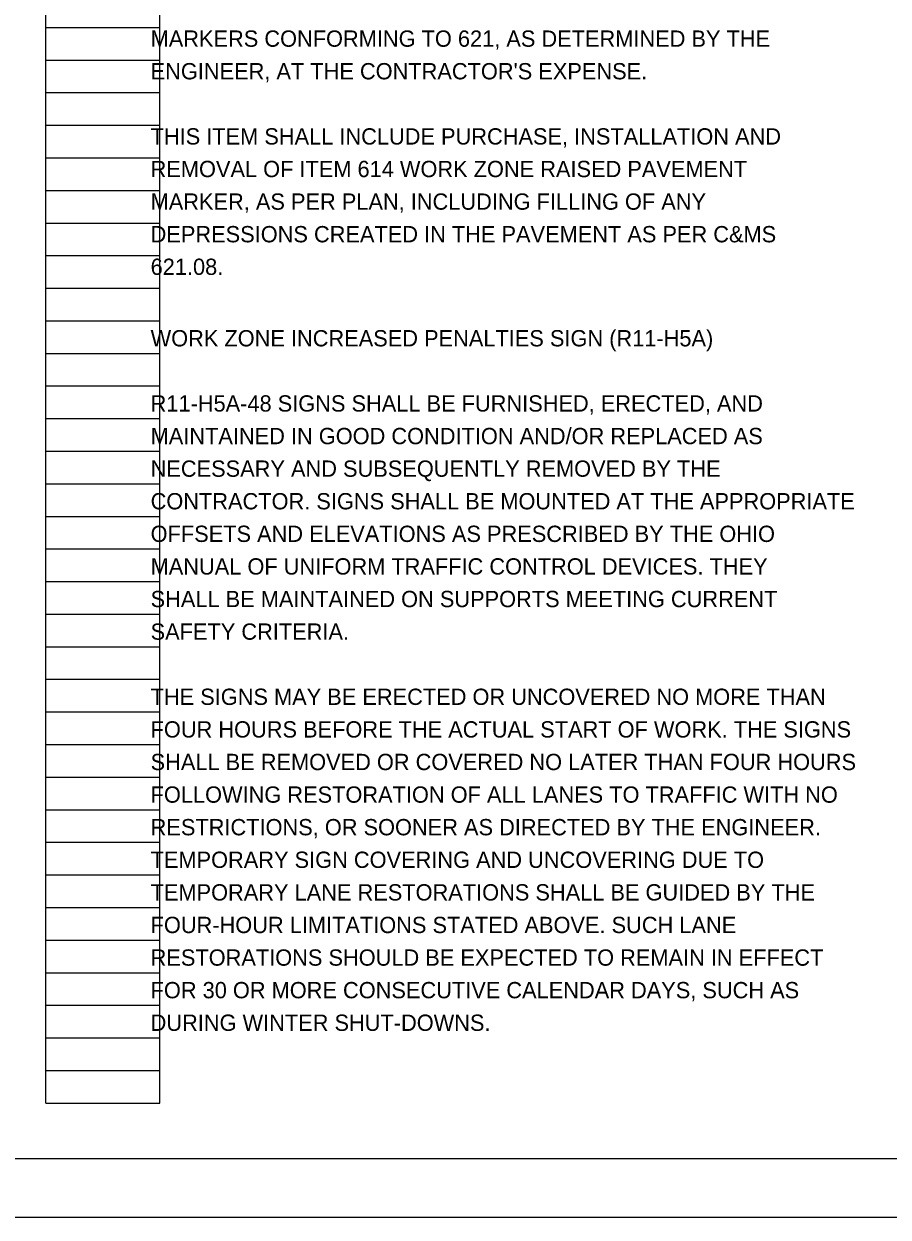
# Model space of a CAD drawing. Extents: x 0 to 34, y 0 to 22.
# Drawn here: x 16.07 to 23.5, y 0 to 10.25 of the extents above; entities that cross this region are included whole.
import ezdxf

# ---------------------------------------------------------------- set-up
doc = ezdxf.new("R2010")
doc.units = 0
for name, color, linetype in [('SH_Border', 7, 'Continuous'), ('SH_Cut_Line', 7, 'Continuous'), ('SH_Data', 7, 'Continuous'), ('SH_Text', 7, 'Continuous')]:
    doc.layers.add(name, color=color, linetype=linetype)

msp = doc.modelspace()

# ---------------------------------------------------------------- linework, layer by layer
at = {"layer": 'SH_Border'}
msp.add_lwpolyline([(1.5, 21.5), (33.5, 21.5), (33.5, 0.5), (1.5, 0.5)], close=True, dxfattribs=at)
at = {"layer": 'SH_Cut_Line'}
msp.add_lwpolyline([(0, 0), (34, 0), (34, 22), (0, 22)], close=True, dxfattribs=at)
at = {"layer": 'SH_Data'}
for p, q in [((16.26, 0.98), (16.26, 21.14)), ((17.24, 0.98), (17.24, 21.14)), ((16.26, 10.22), (17.24, 10.22)), ((16.26, 9.94), (17.24, 9.94)), ((16.26, 9.66), (17.24, 9.66)), ((16.26, 9.38), (17.24, 9.38)), ((16.26, 9.1), (17.24, 9.1)), ((16.26, 8.82), (17.24, 8.82)), ((16.26, 8.54), (17.24, 8.54)), ((16.26, 8.26), (17.24, 8.26)), ((16.26, 7.98), (17.24, 7.98)), ((16.26, 7.7), (17.24, 7.7)), ((16.26, 7.42), (17.24, 7.42)), ((16.26, 7.14), (17.24, 7.14)), ((16.26, 6.86), (17.24, 6.86)), ((16.26, 6.58), (17.24, 6.58)), ((16.26, 6.3), (17.24, 6.3)), ((16.26, 6.02), (17.24, 6.02)), ((16.26, 5.74), (17.24, 5.74)), ((16.26, 5.46), (17.24, 5.46)), ((16.26, 5.18), (17.24, 5.18)), ((16.26, 4.9), (17.24, 4.9)), ((16.26, 4.62), (17.24, 4.62)), ((16.26, 4.34), (17.24, 4.34)), ((16.26, 4.06), (17.24, 4.06)), ((16.26, 3.78), (17.24, 3.78)), ((16.26, 3.5), (17.24, 3.5)), ((16.26, 3.22), (17.24, 3.22)), ((16.26, 2.94), (17.24, 2.94)), ((16.26, 2.66), (17.24, 2.66)), ((16.26, 2.38), (17.24, 2.38)), ((16.26, 2.1), (17.24, 2.1)), ((16.26, 1.82), (17.24, 1.82)), ((16.26, 1.54), (17.24, 1.54)), ((16.26, 1.26), (17.24, 1.26)), ((16.26, 0.98), (17.24, 0.98))]:
    msp.add_line(p, q, dxfattribs=at)

# ---------------------------------------------------------------- texts
at = {"layer": 'SH_Text'}
for s, p in [('MARKERS CONFORMING TO 621, AS DETERMINED BY THE', (17.16, 10.054)), ("ENGINEER, AT THE CONTRACTOR'S EXPENSE.", (17.16, 9.774)), ('THIS ITEM SHALL INCLUDE PURCHASE, INSTALLATION AND', (17.16, 9.214)), ('REMOVAL OF ITEM 614 WORK ZONE RAISED PAVEMENT', (17.16, 8.934)), ('MARKER, AS PER PLAN, INCLUDING FILLING OF ANY', (17.16, 8.654)), ('DEPRESSIONS CREATED IN THE PAVEMENT AS PER C&MS', (17.16, 8.374)), ('621.08.', (17.16, 8.094)), ('WORK ZONE INCREASED PENALTIES SIGN (R11-H5A)', (17.16, 7.48)), ('R11-H5A-48 SIGNS SHALL BE FURNISHED, ERECTED, AND', (17.16, 6.92)), ('MAINTAINED IN GOOD CONDITION AND/OR REPLACED AS', (17.16, 6.64)), ('NECESSARY AND SUBSEQUENTLY REMOVED BY THE', (17.16, 6.36)), ('CONTRACTOR. SIGNS SHALL BE MOUNTED AT THE APPROPRIATE', (17.16, 6.08)), ('OFFSETS AND ELEVATIONS AS PRESCRIBED BY THE OHIO', (17.16, 5.8)), ('MANUAL OF UNIFORM TRAFFIC CONTROL DEVICES. THEY', (17.16, 5.52)), ('SHALL BE MAINTAINED ON SUPPORTS MEETING CURRENT', (17.16, 5.24)), ('SAFETY CRITERIA.', (17.16, 4.96)), ('THE SIGNS MAY BE ERECTED OR UNCOVERED NO MORE THAN', (17.16, 4.4)), ('FOUR HOURS BEFORE THE ACTUAL START OF WORK. THE SIGNS', (17.16, 4.12)), ('SHALL BE REMOVED OR COVERED NO LATER THAN FOUR HOURS', (17.16, 3.84)), ('FOLLOWING RESTORATION OF ALL LANES TO TRAFFIC WITH NO', (17.16, 3.56)), ('RESTRICTIONS, OR SOONER AS DIRECTED BY THE ENGINEER.', (17.16, 3.28)), ('TEMPORARY SIGN COVERING AND UNCOVERING DUE TO', (17.16, 3)), ('TEMPORARY LANE RESTORATIONS SHALL BE GUIDED BY THE', (17.16, 2.72)), ('FOUR-HOUR LIMITATIONS STATED ABOVE. SUCH LANE', (17.16, 2.44)), ('RESTORATIONS SHOULD BE EXPECTED TO REMAIN IN EFFECT', (17.16, 2.16)), ('FOR 30 OR MORE CONSECUTIVE CALENDAR DAYS, SUCH AS', (17.16, 1.88)), ('DURING WINTER SHUT-DOWNS.', (17.16, 1.6))]:
    msp.add_text(s, height=0.14, dxfattribs=at).set_placement(p)

doc.saveas('drawing.dxf')
